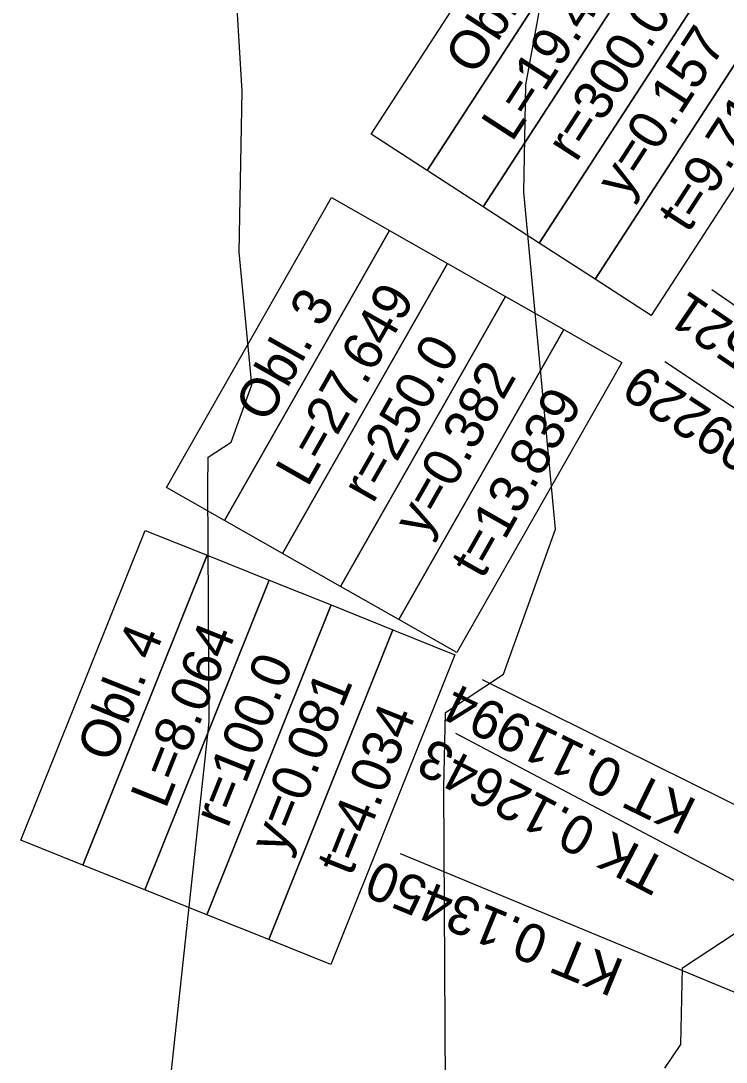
# Model space of a CAD drawing. Extents: x -549394 to -546608, y -1037055 to -1033629.
# Drawn here: x -547669.9 to -547606.6, y -1035190.9 to -1035097.3 of the extents above; entities that cross this region are included whole.
import ezdxf

# ---------------------------------------------------------------- set-up
doc = ezdxf.new("R2010")
doc.units = 0
for name, color, linetype in [('hlavni_vrst', 7, 'Continuous'), ('norm_vrst', 7, 'Continuous'), ('x_popis_oblouky_C1', 7, 'Continuous')]:
    doc.layers.add(name, color=color, linetype=linetype)

msp = doc.modelspace()

# ---------------------------------------------------------------- linework, layer by layer
at = {"layer": 'hlavni_vrst'}
for p, q in [((-547650.053, -1035103.659), (-547650.971, -1035088.226)), ((-547650.315, -1035118.134), (-547650.053, -1035103.659)), ((-547649.191, -1035130.07), (-547650.315, -1035118.134)), ((-547651.039, -1035135.208), (-547649.191, -1035130.07)), ((-547653.091, -1035136.562), (-547651.039, -1035135.208)), ((-547653.144, -1035139.228), (-547653.091, -1035136.562)), ((-547653.022, -1035160.364), (-547653.144, -1035139.228)), ((-547659.241, -1035218.222), (-547653.022, -1035160.364))]:
    msp.add_line(p, q, dxfattribs=at)
at = {"layer": 'norm_vrst'}
for p, q in [((-547624.563, -1035103.1), (-547617.563, -1035064.714)), ((-547624.737, -1035112.739), (-547624.563, -1035103.1)), ((-547621.884, -1035143.039), (-547624.737, -1035112.739)), ((-547626.575, -1035156.081), (-547621.884, -1035143.039)), ((-547631.786, -1035159.519), (-547626.575, -1035156.081)), ((-547631.919, -1035166.286), (-547631.786, -1035159.519)), ((-547631.61, -1035219.94), (-547631.919, -1035166.286)), ((-547610.48, -1035182.476), (-547604.177, -1035178.318)), ((-547610.616, -1035189.354), (-547610.48, -1035182.476)), ((-547612.073, -1035191.488), (-547610.616, -1035189.354))]:
    msp.add_line(p, q, dxfattribs=at)
at = {"layer": 'x_popis_oblouky_C1'}
for points in [[(-547638.459, -1035107.515), (-547622.137, -1035082.344), (-547617.103, -1035085.608), (-547633.424, -1035110.78)], [(-547633.424, -1035110.78), (-547617.103, -1035085.608), (-547612.068, -1035088.872), (-547628.39, -1035114.044)], [(-547628.39, -1035114.044), (-547612.068, -1035088.872), (-547607.034, -1035092.137), (-547623.356, -1035117.308)], [(-547623.356, -1035117.308), (-547607.034, -1035092.137), (-547602, -1035095.401), (-547618.321, -1035120.573)], [(-547618.321, -1035120.573), (-547602, -1035095.401), (-547596.966, -1035098.665), (-547613.287, -1035123.837)], [(-547656.845, -1035139.292), (-547642.018, -1035113.212), (-547636.802, -1035116.178), (-547651.629, -1035142.258)], [(-547651.629, -1035142.258), (-547636.802, -1035116.178), (-547631.586, -1035119.143), (-547646.413, -1035145.223)], [(-547646.413, -1035145.223), (-547631.586, -1035119.143), (-547626.37, -1035122.109), (-547641.197, -1035148.189)], [(-547641.197, -1035148.189), (-547626.37, -1035122.109), (-547621.154, -1035125.074), (-547635.981, -1035151.154)], [(-547635.981, -1035151.154), (-547621.154, -1035125.074), (-547615.938, -1035128.04), (-547630.765, -1035154.119)], [(-547669.935, -1035170.997), (-547658.771, -1035143.151), (-547653.202, -1035145.384), (-547664.366, -1035173.229)], [(-547664.366, -1035173.229), (-547653.202, -1035145.384), (-547647.633, -1035147.616), (-547658.796, -1035175.462)], [(-547658.796, -1035175.462), (-547647.633, -1035147.616), (-547642.064, -1035149.849), (-547653.227, -1035177.695)], [(-547653.227, -1035177.695), (-547642.064, -1035149.849), (-547636.495, -1035152.082), (-547647.658, -1035179.927)], [(-547647.658, -1035179.927), (-547636.495, -1035152.082), (-547630.926, -1035154.315), (-547642.089, -1035182.16)]]:
    msp.add_lwpolyline(points, close=True, dxfattribs=at)
for points in [[(-547573.781, -1035145.01), (-547607.833, -1035121.512)], [(-547577.633, -1035150.95), (-547612.058, -1035128.001)], [(-547591.366, -1035174.932), (-547628.442, -1035156.571)], [(-547594.278, -1035180.74), (-547630.858, -1035161.41)], [(-547597.598, -1035188.086), (-547635.806, -1035172.216)]]:
    msp.add_lwpolyline(points, dxfattribs=at)

# ---------------------------------------------------------------- texts
for s, rotation, p in [('L=19.425', 57.0619, (-547625.806, -1035108.323)), ('Obl. 2', 57.0619, (-547629.098, -1035102.368)), ('r=300.0', 57.0619, (-547620.028, -1035110.124)), ('y=0.157', 57.0619, (-547615.555, -1035113.442)), ('t=9.716', 57.0619, (-547609.972, -1035116.507)), ('L=27.649', 60.40244, (-547644.167, -1035139.361)), ('Obl. 3', 60.40244, (-547647.8, -1035133.608)), ('KT 0.08521', 145.69699, (-547590.044, -1035135.184)), ('r=250.0', 60.40244, (-547638.294, -1035140.822)), ('y=0.382', 60.40244, (-547633.635, -1035143.875)), ('TK 0.09229', 146.61642, (-547594.021, -1035141.407)), ('t=13.839', 60.40244, (-547628.458, -1035147.621)), ('Obl. 4', 68.17598, (-547661.741, -1035164.142)), ('L=8.064', 68.17598, (-547656.931, -1035168.269)), ('r=100.0', 68.17598, (-547651.347, -1035170.004)), ('y=0.081', 68.17598, (-547646.318, -1035172.398)), ('KT 0.11994', 153.96051, (-547609.012, -1035167.477)), ('t=4.034', 68.17598, (-547640.249, -1035174.328)), ('TK 0.12643', 152.45243, (-547611.551, -1035172.912)), ('KT 0.13450', 157.75076, (-547615.554, -1035181.872))]:
    msp.add_text(s, height=3.5, rotation=rotation, dxfattribs=at).set_placement(p)

doc.saveas('drawing.dxf')
